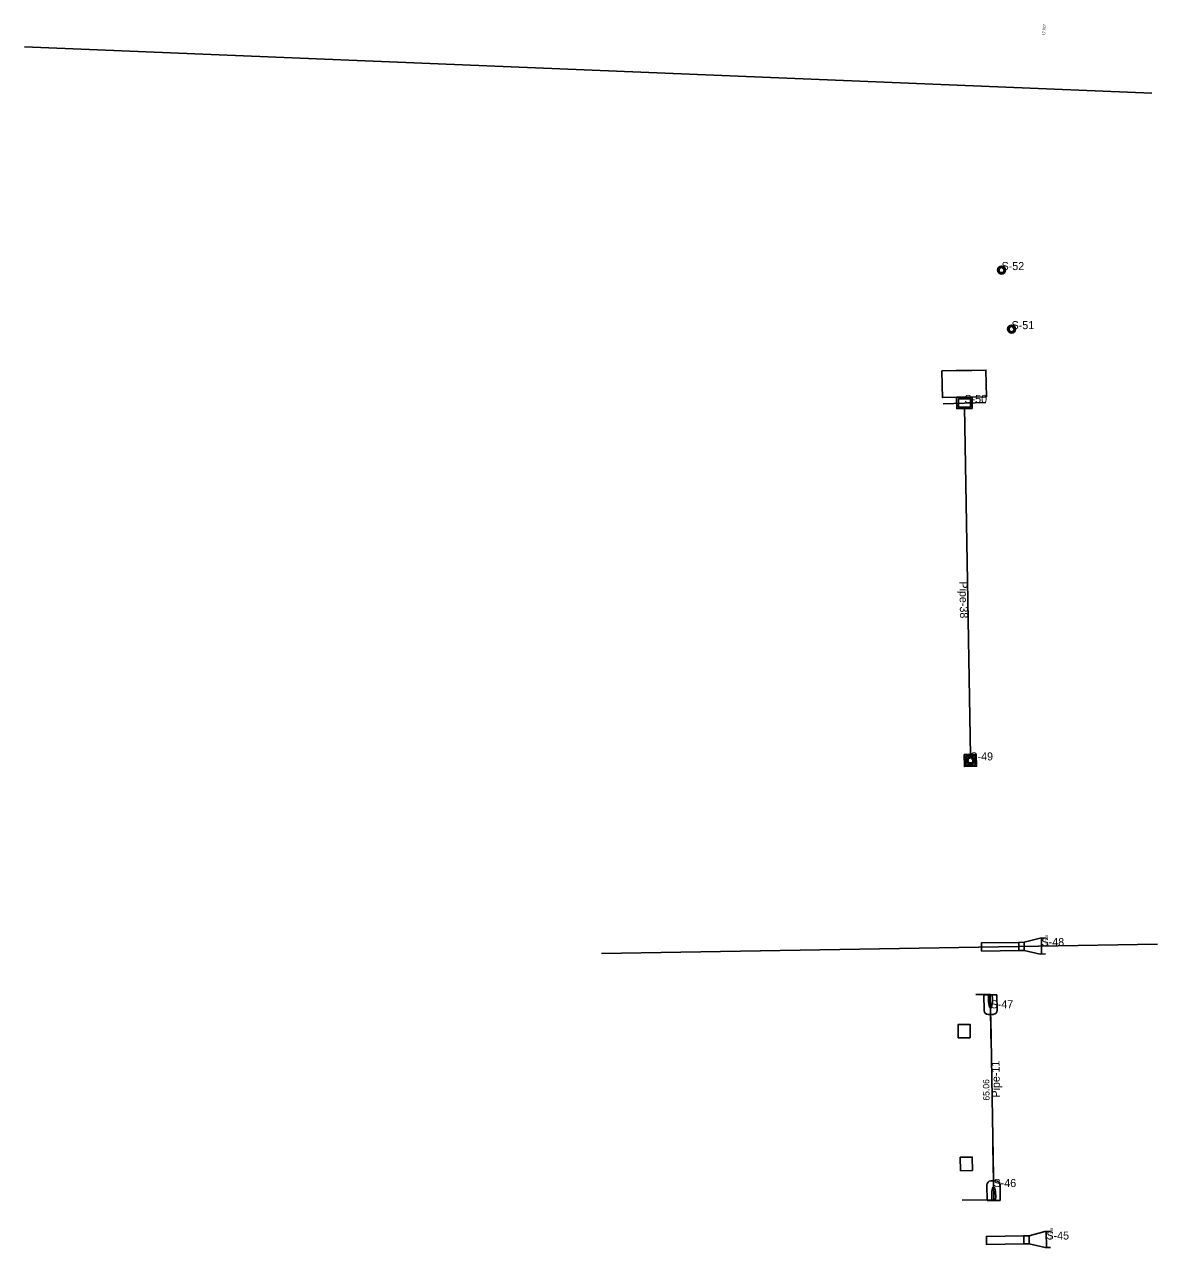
# Model space of a CAD drawing. Extents: x 925371 to 925937, y 853654 to 858024.
# Drawn here: x 925370.5 to 925795.3, y 857035 to 857493.4 of the extents above; entities that cross this region are included whole.
import ezdxf

# ---------------------------------------------------------------- set-up
doc = ezdxf.new("R2010")
doc.units = 0
for name, color, linetype in [('DitchPavt', 7, 'Continuous'), ('GPKDrBack_dp', 7, 'Continuous'), ('GPKDrBottom_dp', 7, 'Continuous'), ('GPKDrCellIns_dp', 7, 'Continuous'), ('GPKDrCentroid_dp', 7, 'Continuous'), ('GPKDrFront_dp', 7, 'Continuous'), ('GPKDrPipe_dp', 7, 'Continuous'), ('GPKDrPipeCir_dp', 7, 'Continuous'), ('InletBottomP', 7, 'Continuous'), ('InletClosedFlume', 7, 'Continuous'), ('InletDBI', 7, 'Continuous'), ('Manhole', 7, 'Continuous'), ('MES', 7, 'Continuous'), ('Miscellaneous5', 7, 'Continuous'), ('Miscellaneous6', 7, 'Continuous'), ('NonPlottingEle_dp', 7, 'Continuous'), ('PipeCulvert', 7, 'Continuous'), ('PipeCulvertSS', 7, 'Continuous')]:
    doc.layers.add(name, color=color, linetype=linetype)

msp = doc.modelspace()

# ---------------------------------------------------------------- linework, layer by layer
at = {"layer": 'DitchPavt'}
for p, q in [((925714.49, 857363.58), (925714.58, 857358.09)), ((925725.66, 857363.77), (925722.74, 857363.72)), ((925743.29, 857149.39), (925729.29, 857149.16)), ((925743.34, 857146.35), (925743.29, 857149.39)), ((925745.12, 857039.41), (925731.13, 857039.17)), ((925745.18, 857036.37), (925745.12, 857039.41))]:
    msp.add_line(p, q, dxfattribs=at)
for points in [[(925722.74, 857363.72), (925719.82, 857363.67), (925714.49, 857363.58)], [(925714.58, 857358.09), (925714.66, 857353.59), (925731.16, 857353.87), (925730.99, 857363.86), (925725.66, 857363.77)], [(925743.34, 857146.35), (925729.34, 857146.11), (925729.29, 857149.16), (925743.29, 857149.39)], [(925729.29, 857149.16), (925729.34, 857146.11), (925743.34, 857146.35)], [(925725.1, 857113.65), (925725.02, 857118.65), (925720.52, 857118.57), (925720.6, 857113.58), (925725.1, 857113.65)], [(925725.94, 857063.91), (925725.86, 857068.91), (925721.36, 857068.83), (925721.45, 857063.83), (925725.94, 857063.91)], [(925745.18, 857036.37), (925731.18, 857036.13), (925731.13, 857039.17), (925745.12, 857039.41)], [(925731.13, 857039.17), (925731.18, 857036.13), (925745.18, 857036.37)]]:
    msp.add_lwpolyline(points, dxfattribs=at)
at = {"layer": 'GPKDrBack_dp'}
for p, q in [((925736.84, 857402.86), (925736.84, 857402.86)), ((925740.57, 857380.71), (925740.57, 857380.71)), ((925722.87, 857353.73), (925722.87, 857353.73)), ((925725.82, 857351.61), (925725.82, 857351.61)), ((925726.64, 857217.6), (925726.64, 857217.6)), ((925726.89, 857217.61), (925726.89, 857217.61)), ((925745.31, 857147.91), (925745.31, 857147.91)), ((925732.61, 857129.72), (925732.61, 857129.72)), ((925733.9, 857052.67), (925733.9, 857052.67)), ((925747.15, 857037.92), (925747.15, 857037.92))]:
    msp.add_line(p, q, dxfattribs=at)
at = {"layer": 'GPKDrBottom_dp'}
for p, q in [((925736.13, 857402.07), (925736.13, 857402.07)), ((925736.84, 857402.36), (925736.84, 857402.36)), ((925737.55, 857402.06), (925737.55, 857402.06)), ((925735.83, 857401.37), (925735.83, 857401.37)), ((925736.12, 857400.66), (925736.12, 857400.66)), ((925736.83, 857401.36), (925736.83, 857401.36)), ((925736.83, 857400.36), (925736.83, 857400.36)), ((925737.54, 857400.65), (925737.54, 857400.65)), ((925737.83, 857401.35), (925737.83, 857401.35)), ((925739.58, 857379.2), (925739.58, 857379.2)), ((925739.87, 857379.91), (925739.87, 857379.91)), ((925739.88, 857378.5), (925739.88, 857378.5)), ((925740.58, 857380.21), (925740.58, 857380.21)), ((925740.58, 857379.21), (925740.58, 857379.21)), ((925741.28, 857379.92), (925741.28, 857379.92)), ((925741.29, 857378.5), (925741.29, 857378.5)), ((925741.58, 857379.21), (925741.58, 857379.21)), ((925740.59, 857378.21), (925740.59, 857378.21)), ((925720.63, 857353.02), (925720.63, 857353.02)), ((925720.66, 857351.52), (925720.66, 857351.52)), ((925722.88, 857353.06), (925722.88, 857353.06)), ((925722.91, 857351.56), (925722.91, 857351.56)), ((925725.13, 857353.1), (925725.13, 857353.1)), ((925725.16, 857351.6), (925725.16, 857351.6)), ((925720.68, 857350.02), (925720.68, 857350.02)), ((925722.93, 857350.06), (925722.93, 857350.06)), ((925725.18, 857350.1), (925725.18, 857350.1)), ((925723.37, 857219.3), (925723.37, 857219.3)), ((925724.43, 857218.27), (925724.43, 857218.27)), ((925725.12, 857219.33), (925725.12, 857219.33)), ((925725.13, 857218.58), (925725.13, 857218.58)), ((925725.84, 857218.3), (925725.84, 857218.3)), ((925726.87, 857219.36), (925726.87, 857219.36)), ((925723.4, 857217.55), (925723.4, 857217.55)), ((925723.42, 857215.8), (925723.42, 857215.8)), ((925724.15, 857217.56), (925724.15, 857217.56)), ((925724.45, 857216.86), (925724.45, 857216.86)), ((925725.15, 857217.58), (925725.15, 857217.58)), ((925725.15, 857217.58), (925725.15, 857217.58)), ((925725.16, 857216.58), (925725.16, 857216.58)), ((925725.17, 857215.83), (925725.17, 857215.83)), ((925725.86, 857216.88), (925725.86, 857216.88)), ((925726.14, 857217.59), (925726.14, 857217.59)), ((925726.89, 857217.61), (925726.89, 857217.61)), ((925726.92, 857215.86), (925726.92, 857215.86)), ((925751.81, 857148.02), (925751.81, 857148.02)), ((925732.7, 857124.69), (925732.7, 857124.69)), ((925733.82, 857057.7), (925733.82, 857057.7)), ((925753.65, 857038.03), (925753.65, 857038.03))]:
    msp.add_line(p, q, dxfattribs=at)
at = {"layer": 'GPKDrCellIns_dp'}
for p, q in [((925736.83, 857401.36), (925736.83, 857401.36)), ((925740.58, 857379.21), (925740.58, 857379.21)), ((925722.91, 857351.56), (925722.91, 857351.56)), ((925725.15, 857217.58), (925725.15, 857217.58)), ((925725.15, 857217.58), (925725.15, 857217.58)), ((925751.81, 857148.02), (925751.81, 857148.02)), ((925732.7, 857124.69), (925732.7, 857124.69)), ((925733.82, 857057.7), (925733.82, 857057.7)), ((925753.65, 857038.03), (925753.65, 857038.03))]:
    msp.add_line(p, q, dxfattribs=at)
at = {"layer": 'GPKDrCentroid_dp'}
for p, q in [((925736.83, 857401.36), (925736.83, 857401.36)), ((925740.58, 857379.21), (925740.58, 857379.21)), ((925725.15, 857217.58), (925725.15, 857217.58))]:
    msp.add_line(p, q, dxfattribs=at)
at = {"layer": 'GPKDrFront_dp'}
for p, q in [((925736.83, 857399.86), (925736.83, 857399.86)), ((925740.59, 857377.71), (925740.59, 857377.71)), ((925719.99, 857351.51), (925719.99, 857351.51)), ((925722.94, 857349.39), (925722.94, 857349.39)), ((925723.4, 857217.55), (925723.4, 857217.55)), ((925723.65, 857217.55), (925723.65, 857217.55)), ((925753.31, 857148.04), (925753.31, 857148.04)), ((925732.74, 857122.4), (925732.74, 857122.4)), ((925733.78, 857059.99), (925733.78, 857059.99)), ((925755.15, 857038.05), (925755.15, 857038.05))]:
    msp.add_line(p, q, dxfattribs=at)
at = {"layer": 'GPKDrPipe_dp'}
for p, q in [((925720.66, 857351.52), (925720.66, 857351.52)), ((925722.88, 857353.06), (925722.88, 857353.06)), ((925725.16, 857351.6), (925725.16, 857351.6)), ((925722.93, 857350.06), (925722.93, 857350.06)), ((925725.12, 857219.33), (925725.12, 857219.33)), ((925723.4, 857217.55), (925723.4, 857217.55)), ((925725.17, 857215.83), (925725.17, 857215.83)), ((925726.89, 857217.61), (925726.89, 857217.61)), ((925732.76, 857120.72), (925732.76, 857120.72)), ((925733.75, 857061.67), (925733.75, 857061.67))]:
    msp.add_line(p, q, dxfattribs=at)
at = {"layer": 'GPKDrPipeCir_dp'}
for centre in [(925736.83, 857401.36), (925740.58, 857379.21), (925725.15, 857217.58)]:
    msp.add_circle(centre, 0.958, dxfattribs=at)
at = {"layer": 'InletBottomP'}
for points in [[(925727.36, 857219.86), (925727.43, 857215.37), (925722.93, 857215.29), (925722.86, 857219.79)], [(925723.37, 857219.3), (925726.87, 857219.36), (925726.92, 857215.86), (925723.42, 857215.8)]]:
    msp.add_lwpolyline(points, close=True, dxfattribs=at)
at = {"layer": 'InletClosedFlume'}
for p, q in [((925745.29, 857149.43), (925751.26, 857151.01)), ((925745.34, 857146.39), (925745.29, 857149.43)), ((925753.26, 857151.04), (925751.26, 857151.01)), ((925751.86, 857145.02), (925751.76, 857151.01)), ((925751.36, 857145.01), (925745.34, 857146.39)), ((925753.36, 857145.04), (925751.36, 857145.01)), ((925747.12, 857039.44), (925753.1, 857041.02)), ((925747.18, 857036.4), (925747.12, 857039.44)), ((925755.1, 857041.05), (925753.1, 857041.02)), ((925753.7, 857035.03), (925753.6, 857041.03)), ((925753.2, 857035.02), (925747.18, 857036.4)), ((925755.2, 857035.05), (925753.2, 857035.02))]:
    msp.add_line(p, q, dxfattribs=at)
for points in [[(925745.34, 857146.39), (925743.34, 857146.35), (925743.29, 857149.39), (925745.29, 857149.43)], [(925747.18, 857036.4), (925745.18, 857036.37), (925745.12, 857039.41), (925747.12, 857039.44)]]:
    msp.add_lwpolyline(points, dxfattribs=at)
at = {"layer": 'InletDBI'}
for p, q in [((925725.79, 857353.77), (925719.95, 857353.68)), ((925719.95, 857353.68), (925720.03, 857349.34)), ((925725.13, 857353.28), (925720.63, 857353.21)), ((925720.63, 857353.21), (925720.68, 857349.83)), ((925725.13, 857353.1), (925720.63, 857353.02)), ((925725.18, 857349.91), (925725.13, 857353.28)), ((925725.86, 857349.44), (925725.79, 857353.77)), ((925720.03, 857349.34), (925725.86, 857349.44)), ((925720.68, 857350.02), (925725.18, 857350.1)), ((925720.68, 857349.83), (925725.18, 857349.91))]:
    msp.add_line(p, q, dxfattribs=at)
at = {"layer": 'Manhole'}
for p, q in [((925735.58, 857401.39), (925735.78, 857401.39)), ((925735.94, 857402.23), (925736.08, 857402.09)), ((925735.97, 857402.27), (925736.11, 857402.13)), ((925736.82, 857402.61), (925736.82, 857402.41)), ((925736.87, 857402.61), (925736.87, 857402.41)), ((925737.71, 857402.26), (925737.56, 857402.12)), ((925737.74, 857402.22), (925737.6, 857402.08)), ((925735.58, 857401.34), (925735.78, 857401.34)), ((925736.07, 857400.64), (925735.93, 857400.5)), ((925736.1, 857400.6), (925735.96, 857400.46)), ((925736.8, 857400.31), (925736.8, 857400.11)), ((925736.85, 857400.31), (925736.85, 857400.11)), ((925737.56, 857400.59), (925737.69, 857400.45)), ((925737.59, 857400.63), (925737.73, 857400.49)), ((925737.89, 857401.38), (925738.08, 857401.38)), ((925737.89, 857401.33), (925738.08, 857401.33)), ((925739.33, 857379.23), (925739.53, 857379.23)), ((925739.33, 857379.17), (925739.53, 857379.18)), ((925739.67, 857380.07), (925739.81, 857379.93)), ((925739.82, 857378.48), (925739.68, 857378.34)), ((925739.71, 857380.11), (925739.85, 857379.97)), ((925740.55, 857380.46), (925740.55, 857380.26)), ((925740.6, 857380.46), (925740.6, 857380.26)), ((925741.44, 857380.11), (925741.3, 857379.97)), ((925741.48, 857380.08), (925741.34, 857379.94)), ((925741.35, 857378.49), (925741.49, 857378.35)), ((925741.63, 857379.24), (925741.83, 857379.24)), ((925741.63, 857379.19), (925741.83, 857379.19)), ((925739.86, 857378.44), (925739.72, 857378.3)), ((925740.56, 857378.16), (925740.56, 857377.96)), ((925740.61, 857378.16), (925740.61, 857377.96)), ((925741.31, 857378.45), (925741.45, 857378.31)), ((925724.37, 857218.29), (925724.23, 857218.43)), ((925724.41, 857218.33), (925724.26, 857218.46)), ((925725.1, 857218.63), (925725.1, 857218.83)), ((925725.15, 857218.63), (925725.15, 857218.83)), ((925726, 857218.49), (925725.86, 857218.35)), ((925726.03, 857218.46), (925725.89, 857218.32)), ((925724.09, 857217.59), (925723.89, 857217.58)), ((925724.09, 857217.53), (925723.9, 857217.53)), ((925724.4, 857216.84), (925724.26, 857216.7)), ((925724.43, 857216.8), (925724.29, 857216.66)), ((925725.14, 857216.33), (925725.14, 857216.53)), ((925725.19, 857216.33), (925725.19, 857216.53)), ((925726.03, 857216.69), (925725.88, 857216.83)), ((925726.06, 857216.73), (925725.92, 857216.86)), ((925726.39, 857217.62), (925726.2, 857217.62)), ((925726.4, 857217.57), (925726.2, 857217.57))]:
    msp.add_line(p, q, dxfattribs=at)
for centre, radius in [((925736.83, 857401.36), 1.5), ((925736.83, 857401.36), 1.25), ((925736.83, 857401.36), 1.05), ((925736.83, 857401.36), 1), ((925740.58, 857379.21), 1.5), ((925740.58, 857379.21), 1.25), ((925740.58, 857379.21), 1.05), ((925740.58, 857379.21), 1), ((925725.15, 857217.58), 1.5), ((925725.15, 857217.58), 1.25), ((925725.15, 857217.58), 1.05), ((925725.15, 857217.58), 1)]:
    msp.add_circle(centre, radius, dxfattribs=at)
at = {"layer": 'MES'}
for p, q in [((925730.15, 857129.68), (925735.07, 857129.76)), ((925730.25, 857123.86), (925730.15, 857129.68)), ((925731.9, 857127.96), (925731.91, 857129.71)), ((925733.39, 857127.99), (925733.32, 857129.73)), ((925735.07, 857129.76), (925735.17, 857123.94)), ((925733.7, 857122.42), (925731.78, 857122.39)), ((925732.74, 857122.4), (925732.76, 857120.72)), ((925731.44, 857052.63), (925731.34, 857058.45)), ((925732.82, 857059.97), (925734.74, 857060)), ((925733.78, 857059.99), (925733.75, 857061.67)), ((925736.26, 857058.53), (925736.36, 857052.71)), ((925733.13, 857054.4), (925733.2, 857052.66)), ((925734.62, 857054.43), (925734.61, 857052.68)), ((925736.36, 857052.71), (925731.44, 857052.63))]:
    msp.add_line(p, q, dxfattribs=at)
for centre, start, end in [((925731.75, 857123.88), 180.9573, 270.9573), ((925733.67, 857123.92), 270.9573, 0.9573), ((925732.84, 857058.47), 90.9573, 180.9573), ((925734.76, 857058.51), 0.9573, 90.9573)]:
    msp.add_arc(centre, 1.5, start, end, dxfattribs=at)
for centre, major_axis in [((925732.65, 857127.69), (0.05, -3)), ((925733.87, 857054.7), (-0.05, 3))]:
    msp.add_ellipse(centre, major_axis=major_axis, ratio=0.25, start_param=4.617261, end_param=7.949056, dxfattribs=at)
at = {"layer": 'Miscellaneous5'}
msp.add_line((925793.17, 857467.66), (925370.5, 857485.06), dxfattribs=at)
at = {"layer": 'Miscellaneous6'}
msp.add_line((925795.3, 857148.75), (925586.88, 857145.2), dxfattribs=at)
at = {"layer": 'NonPlottingEle_dp'}
for points in [[(925732.95, 857109.9), (925732.61, 857129.89), (925727.19, 857129.8)], [(925733.56, 857072.93), (925733.9, 857052.93), (925722.08, 857052.73)]]:
    msp.add_lwpolyline(points, dxfattribs=at)
at = {"layer": 'PipeCulvert'}
for p, q in [((925722.91, 857351.51), (925714.91, 857351.28)), ((925722.91, 857351.51), (925730.9, 857351.74)), ((925733.75, 857061.67), (925732.76, 857120.72))]:
    msp.add_line(p, q, dxfattribs=at)
at = {"layer": 'PipeCulvertSS'}
msp.add_line((925722.93, 857350.06), (925725.12, 857219.33), dxfattribs=at)

# ---------------------------------------------------------------- texts
at = {"layer": 'NonPlottingEle_dp'}
for s, height, rotation, p in [('17.017', 1, 87.0544, (925753.15, 857489.33)), ('Pipe-38', 3, 270.9573, (925721.02, 857284.64)), ('16.710', 1, 90.9573, (925754.31, 857148.05)), ('Pipe-11', 3, 90.9573, (925736.26, 857091.25)), ('65.06', 2.4, 90.9741, (925732.34, 857090.11)), ('17.259', 1, 90.9573, (925756.15, 857038.23))]:
    msp.add_text(s, height=height, rotation=rotation, dxfattribs=at).set_placement(p)
for s, p in [('S-52', (925736.83, 857401.36)), ('S-51', (925740.58, 857379.21)), ('S-50', (925722.91, 857351.56)), ('S-49', (925725.15, 857217.58)), ('S-48', (925751.81, 857148.02)), ('S-47', (925732.7, 857124.69)), ('S-46', (925733.82, 857057.7)), ('S-45', (925753.65, 857038.03))]:
    msp.add_text(s, height=3, dxfattribs=at).set_placement(p)

doc.saveas('drawing.dxf')
